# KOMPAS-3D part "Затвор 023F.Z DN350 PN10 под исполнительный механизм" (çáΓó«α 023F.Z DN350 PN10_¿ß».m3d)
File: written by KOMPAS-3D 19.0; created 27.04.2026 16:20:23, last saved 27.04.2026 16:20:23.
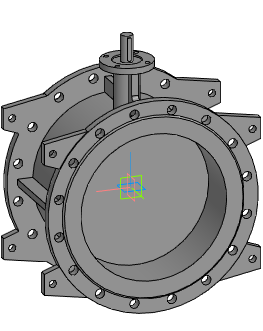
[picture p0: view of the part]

Document properties: Автор: Евгений; Полное имя файла: Z:\3.Личные\kachalov\3d для проектировщиков\1.7 Тип 023F.Z Затвор дисковый поворотный фланцевый с двумя эксцентриками\Затвор 023F.Z DN200-DN1600_исп\_stp_Затвор 023F.Z DN200-DN1600_исп\Затвор 023F.Z DN350 PN10_исп.m3d

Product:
- Part/product: Затвор 023F.Z DN350 PN10 под исполнительный механизм

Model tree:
1. Операция без истории:1  (labels: Затвор 023F.Z DN350 PN10 под исполнительный механизм)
